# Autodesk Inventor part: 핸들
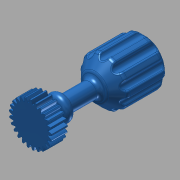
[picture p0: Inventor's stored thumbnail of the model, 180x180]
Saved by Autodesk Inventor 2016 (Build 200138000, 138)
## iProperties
Created: 2017-04
Part Number: 핸들
Material: 강철, 연강
Document SubType Name: Modeling
Designer: mduedu
Categories: <?xml version="1.0" encoding="UTF-16"?> <MemberInstance><Categories><FamilyTemplate><FamilyTemplateParameter ValueType="xs:double" Id="1" ObjectReferenceKey="da
Density: 7.86 g/cm^3
Appearance: 청록색
Mass: 209.322 g
Surface Area: 78.6047 cm^2
Volume: 26.6313 cm^3
CustomPartVersion: 1
Author: mduedu
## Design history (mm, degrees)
sketch "Sketch1"
  geometry: C1 r 13.5 at (0, 0)
  constraints: 1 centre point
  dimensions: "d0" = 27 diameter of C1 (= da_da)
extrude "Extrusion1" new body sketch "Sketch1" distance "d1" = 10 (= da_b); taper "d2" = 0 deg
workplane "Work Plane2"
sketch "Sketch2"
  geometry: C1 r 13.5 at (0, 0) reference; C2 r 12.5 at (0, 0)
  constraints: 1 centre point, 1 coincident
  dimensions: "d3" = 25 diameter of C2 (= da_dw)
feature "피치 지름" sketch "Sketch2" dims "d4" = 10, "d5" = 0
workplane "Work Plane8"
workplane "Work Plane9"
feature "스퍼 기어" dims "da_b" = 10, "da_d" = 25, "da_aw" = 25, "da_da" = 27, "da_df" = 22.5, "da_dw" = 25, angle "da_beta" = 0 deg, "da_lefttooth" = 0, "da_righttooth" = 0
sketch "스케치3"
  geometry: C1 r 5 at (0, 0); 1 further point
  constraints: 1 centre point, 1 coincident
  dimensions: "d49" = 10 diameter of C1
extrude "돌출2" join sketch "스케치3" distance "d50" = 60; taper "d51" = 0 deg
sketch "스케치4"
  geometry: C1 r 15 at (0, 0); 1 further point
  constraints: 1 centre point, 1 coincident
  dimensions: "d52" = 30 diameter of C1
extrude "돌출3" join sketch "스케치4" distance "d53" = 30; taper "d54" = 0 deg
chamfer "모따기1" distance "d55" = 7; stored, may be unused: second distance "d56" = 2, angle "d57" = 45 deg
sketch "스케치5"
  geometry: L1 (0, 2.2)-(0, -13.2) reference; L2 (0, -5)-(8, -5); L3 (8, -5)-(8, -11); L4 (8, -11)-(0, -11); L5 (0, -11)-(0, -5); 1 further point
  constraints: 8 end point, 2 parallel, 1 horizontal, 1 perpendicular, 1 point on line
  dimensions: "d58" = 5 distance from line of L2 point (0, 0); "d59" = 6 distance of L2.end L3.end; "d60" = 16 diameter of L3 L1
revolve "회전1" sketch "스케치5" stored, may be unused: angle "d61" = 90 deg
fillet "모깎기1" dims "d62" = 3
fillet "모깎기2" dims "d65" = 3
sketch "스케치9"
  geometry: L1 (15, -60)-(-15, -60) reference; L2 (0, -60)-(0, 0); L3 (0, -66.771)-(0, -60); A1 r 20 centre (0, -46.771) between (0, -66.771) and (15, -60)
  constraints: 4 end point, 2 point on circle, 1 centre point, 1 collinear, 1 line through centre, 1 midpoint, 1 perpendicular
  dimensions: "d84" = 20 radius of A1
revolve "회전4" sketch "스케치9" stored, may be unused: angle "d86" = 90 deg
fillet "모깎기3" dims "d72" = 3
sketch "스케치6"
  geometry: C1 r 2.5 at (0, 15); 2 further points
  constraints: 2 vertical alignment, 1 centre point, 1 other
  dimensions: "d66" = 5 diameter of C1
extrude "돌출4" cut sketch "스케치6" stored distance "d67" = 60; taper "d68" = 0 deg
fillet "모깎기4" dims "d73" = 1
node "작업 평면12"
sketch "스케치10"
  geometry: C1 r 6 at (0, 0); 1 further point
  constraints: 1 centre point, 1 coincident
  dimensions: "d87" = 12 diameter of C1
extrude "돌출5" cut sketch "스케치10" distance "d88" = 5; taper "d89" = 0 deg
fillet "모깎기5" dims "d90" = 1
body "Solid1"
pattern_circular "원형 패턴2" dims angle "d75" = 360 deg
body "Srf1"
other parameters: "d16" = 25 (= da_aw), "d17" = 0, "d34" = 1.25664 (computed from da_z), "d39" = 0, "d41" = 0, "d43" = 25 (= da_aw), "d46" = 25 (= da_aw), "d47" = 0, "d48" = 0
